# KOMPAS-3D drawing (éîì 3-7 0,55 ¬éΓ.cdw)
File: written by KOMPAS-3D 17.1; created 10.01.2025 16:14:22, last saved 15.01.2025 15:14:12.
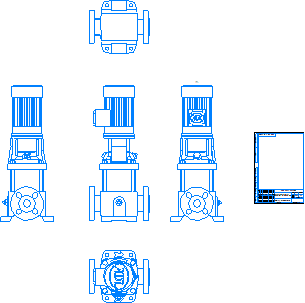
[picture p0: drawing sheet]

Sheet 1: A4, portrait

Title block, sheet 1: name: ВМН 3-7 0,55 кВт; designation: ВМН 3-7 0,55 кВт; material: Сталь 10  ГОСТ 1050-2013; mass: 69,28; sheets: 1; sheet format: A4; stored path: \\adlc.lan\data\АДЛ_ПКД\3D-модели\ADL production\Насосы ГРАНПАМП\Насосы ВМН\ВМН3\KOMPAS 3D\3-7 0,55 кВт _ ВМН.cdw

Views: Проекционный вид 2, Проекционный вид 3, Проекционный вид 4, Проекционный вид 5
Referenced files in \\adlc.lan\data\АДЛ_ПКД\3D-модели\ADL production\Насосы ГРАНПАМП\Насосы ВМН\ВМН3\KOMPAS 3D\: ВМН 3-7 0,55 кВт.m3d
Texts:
  Andrey
  АДЛ
Dimensions and other numbers on the sheet: 1:1; 1; 69,28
